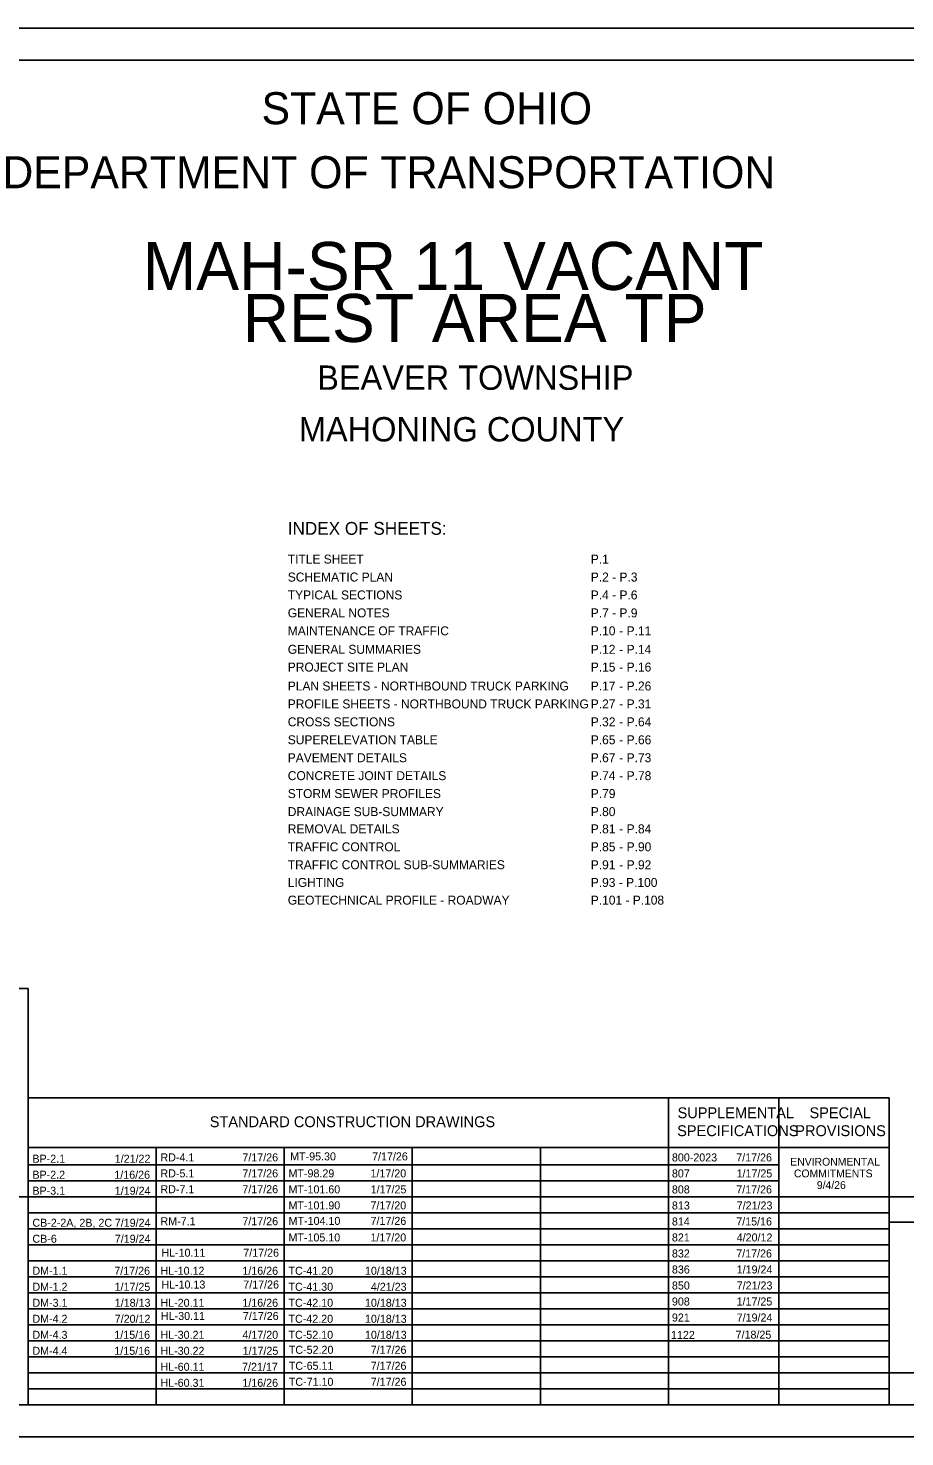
# Model space of a CAD drawing. Extents: x 0 to 36.9, y 0 to 22.
# Drawn here: x 10.15 to 23.84, y 0 to 22 of the extents above; entities that cross this region are included whole.
import ezdxf

# ---------------------------------------------------------------- set-up
doc = ezdxf.new("R2010")
doc.units = 0
for name, color, linetype in [('SH_Border', 7, 'Continuous'), ('SH_Cut_Line', 7, 'Continuous'), ('SH_Data', 7, 'Continuous'), ('SH_Text', 7, 'Continuous')]:
    doc.layers.add(name, color=color, linetype=linetype)

msp = doc.modelspace()

# ---------------------------------------------------------------- linework, layer by layer
at = {"layer": 'SH_Border'}
msp.add_lwpolyline([(1.5, 21.5), (33.5, 21.5), (33.5, 0.5), (1.5, 0.5)], close=True, dxfattribs=at)
at = {"layer": 'SH_Cut_Line'}
msp.add_lwpolyline([(0, 0), (34, 0), (34, 22), (0, 22)], close=True, dxfattribs=at)
at = {"layer": 'SH_Data'}
for p, q in [((10.15, 5.292), (23.6, 5.292)), ((10.15, 0.5), (10.15, 5.292)), ((20.15, 0.5), (20.15, 5.292)), ((21.875, 0.5), (21.875, 5.292)), ((23.6, 0.5), (23.6, 5.292)), ((10.15, 4.521), (23.6, 4.521)), ((12.15, 0.5), (12.15, 4.521)), ((14.15, 0.5), (14.15, 4.521)), ((16.15, 0.5), (16.15, 4.521)), ((18.15, 0.5), (18.15, 4.521)), ((10.15, 4.25), (21.875, 4.25)), ((10.15, 4), (21.875, 4)), ((10.15, 3.75), (23.6, 3.75)), ((23.6, 0.5), (23.6, 3.75)), ((23.6, 3.75), (26.4, 3.75)), ((10.15, 3.5), (23.6, 3.5)), ((23.6, 3.35), (26.4, 3.35)), ((10.15, 3.25), (23.6, 3.25)), ((10.15, 3), (23.6, 3)), ((10.15, 2.75), (23.6, 2.75)), ((10.15, 2.5), (23.6, 2.5)), ((10.15, 2.25), (23.6, 2.25)), ((10.15, 2), (23.6, 2)), ((10.15, 1.75), (23.6, 1.75)), ((10.15, 1.5), (23.6, 1.5)), ((10.15, 1.25), (23.6, 1.25)), ((10.15, 1), (23.6, 1)), ((10.15, 0.75), (23.6, 0.75)), ((23.6, 0.5), (26.4, 0.5))]:
    msp.add_line(p, q, dxfattribs=at)
for points in [[(10.15, 7), (7.35, 7), (7.35, 3.75), (10.15, 3.75)], [(10.15, 3.75), (7.35, 3.75), (7.35, 0.5), (10.15, 0.5)], [(23.6, 0.5), (23.6, 1), (26.4, 1), (26.4, 0.5)]]:
    msp.add_lwpolyline(points, close=True, dxfattribs=at)

# ---------------------------------------------------------------- texts
at = {"layer": 'SH_Text'}
for s, height, p in [('STATE OF OHIO', 0.5, (13.795, 20.5)), ('DEPARTMENT OF TRANSPORTATION', 0.5, (9.747, 19.5)), ('MAH-SR 11 VACANT ', 0.75, (11.94, 17.911)), ('REST AREA TP', 0.75, (13.502, 17.099)), ('BEAVER TOWNSHIP', 0.38, (14.664, 16.352)), ('MAHONING COUNTY', 0.38, (14.378, 15.546)), ('INDEX OF SHEETS:', 0.2, (14.205, 14.088)), ('TITLE SHEET', 0.14, (14.205, 13.638)), ('P.1', 0.14, (18.938, 13.638)), ('SCHEMATIC PLAN', 0.14, (14.205, 13.358)), ('P.2', 0.14, (18.938, 13.358)), ('P.3', 0.14, (19.386, 13.358)), ('TYPICAL SECTIONS', 0.14, (14.205, 13.078)), ('P.4', 0.14, (18.938, 13.078)), (' - ', 0.14, (19.219, 13.358)), ('P.6', 0.14, (19.386, 13.078)), (' - ', 0.14, (19.219, 13.078)), ('GENERAL NOTES', 0.14, (14.205, 12.798)), ('P.7', 0.14, (18.938, 12.798)), (' - ', 0.14, (19.219, 12.798)), ('P.9', 0.14, (19.386, 12.798)), ('MAINTENANCE OF TRAFFIC', 0.14, (14.205, 12.518)), ('P.10', 0.14, (18.938, 12.518)), (' - ', 0.14, (19.331, 12.518)), ('P.11', 0.14, (19.498, 12.518)), ('GENERAL SUMMARIES', 0.14, (14.205, 12.229)), ('P.12', 0.14, (18.938, 12.229)), ('P.14', 0.14, (19.498, 12.229)), (' - ', 0.14, (19.331, 12.229)), ('PROJECT SITE PLAN', 0.14, (14.205, 11.952)), ('P.15', 0.14, (18.938, 11.952)), (' - ', 0.14, (19.331, 11.952)), ('P.16', 0.14, (19.498, 11.952)), ('PLAN SHEETS - NORTHBOUND TRUCK PARKING', 0.14, (14.205, 11.656)), ('P.17', 0.14, (18.938, 11.656)), (' - ', 0.14, (19.331, 11.656)), ('P.26', 0.14, (19.498, 11.656)), ('PROFILE SHEETS - NORTHBOUND TRUCK PARKING', 0.14, (14.205, 11.376)), ('P.27', 0.14, (18.938, 11.376)), ('P.31', 0.14, (19.498, 11.376)), ('CROSS SECTIONS', 0.14, (14.205, 11.096)), ('P.32', 0.14, (18.938, 11.096)), (' - ', 0.14, (19.331, 11.376)), ('P.64', 0.14, (19.498, 11.096)), (' - ', 0.14, (19.331, 11.096)), ('SUPERELEVATION TABLE', 0.14, (14.205, 10.816)), ('P.65', 0.14, (18.938, 10.816)), (' - ', 0.14, (19.331, 10.816)), ('P.66', 0.14, (19.498, 10.816)), ('PAVEMENT DETAILS', 0.14, (14.205, 10.536)), ('P.67', 0.14, (18.938, 10.536)), (' - ', 0.14, (19.331, 10.536)), ('P.73', 0.14, (19.498, 10.536)), ('CONCRETE JOINT DETAILS', 0.14, (14.205, 10.256)), ('P.74', 0.14, (18.938, 10.256)), ('P.78', 0.14, (19.498, 10.256)), (' - ', 0.14, (19.331, 10.256)), ('STORM SEWER PROFILES', 0.14, (14.205, 9.976)), ('P.79', 0.14, (18.938, 9.976)), ('DRAINAGE SUB-SUMMARY', 0.14, (14.205, 9.694)), ('P.80', 0.14, (18.938, 9.694)), ('REMOVAL DETAILS', 0.14, (14.205, 9.425)), ('P.81', 0.14, (18.938, 9.425)), (' - ', 0.14, (19.331, 9.425)), ('P.84', 0.14, (19.498, 9.425)), ('TRAFFIC CONTROL', 0.14, (14.205, 9.145)), ('P.85', 0.14, (18.938, 9.145)), ('P.90', 0.14, (19.498, 9.145)), (' - ', 0.14, (19.331, 9.145)), ('TRAFFIC CONTROL SUB-SUMMARIES', 0.14, (14.205, 8.865)), ('P.91', 0.14, (18.938, 8.864)), (' - ', 0.14, (19.331, 8.864)), ('P.92', 0.14, (19.498, 8.864)), ('LIGHTING', 0.14, (14.205, 8.588)), ('P.93 - P.100', 0.14, (18.938, 8.588)), ('GEOTECHNICAL PROFILE - ROADWAY', 0.14, (14.205, 8.312)), ('P.101 - P.108', 0.14, (18.938, 8.312)), ('SUPPLEMENTAL', 0.17, (20.293, 4.976)), ('SPECIAL', 0.17, (22.354, 4.976)), ('STANDARD CONSTRUCTION DRAWINGS', 0.17, (12.986, 4.836)), ('SPECIFICATIONS', 0.17, (20.287, 4.696)), ('PROVISIONS', 0.17, (22.132, 4.696)), ('BP-2.1', 0.125, (10.216, 4.281)), ('1/21/22', 0.125, (11.502, 4.281)), ('RD-4.1', 0.125, (12.216, 4.302)), ('7/17/26', 0.125, (13.496, 4.302)), ('MT-95.30', 0.125, (14.242, 4.317)), ('7/17/26', 0.125, (15.522, 4.317)), ('800-2023', 0.125, (20.205, 4.301)), ('7/17/26', 0.125, (21.21, 4.301)), ('7/17/26', 0.125, (13.496, 4.052)), ('1/17/20', 0.125, (15.497, 4.052)), ('1/17/25', 0.125, (21.215, 4.051)), ('ENVIRONMENTAL', 0.12154, (22.054, 4.235)), ('BP-2.2', 0.125, (10.216, 4.031)), ('1/16/26', 0.125, (11.496, 4.031)), ('RD-5.1', 0.125, (12.216, 4.052)), ('MT-98.29', 0.125, (14.216, 4.052)), ('807', 0.125, (20.205, 4.051)), ('COMMITMENTS', 0.12154, (22.111, 4.053)), ('9/4/26', 0.1215, (22.469, 3.871)), ('BP-3.1', 0.125, (10.216, 3.781)), ('1/19/24', 0.125, (11.503, 3.781)), ('RD-7.1', 0.125, (12.216, 3.805)), ('7/17/26', 0.125, (13.496, 3.805)), ('MT-101.60', 0.125, (14.216, 3.802)), ('1/17/25', 0.125, (15.5, 3.802)), ('808', 0.125, (20.205, 3.801)), ('7/17/26', 0.125, (21.21, 3.801)), ('MT-101.90', 0.125, (14.216, 3.552)), ('7/17/20', 0.125, (15.497, 3.552)), ('813', 0.125, (20.205, 3.551)), ('7/21/23', 0.125, (21.217, 3.551)), ('CB-2-2A, 2B, 2C', 0.125, (10.216, 3.281)), ('7/19/24', 0.125, (11.503, 3.281)), ('RM-7.1', 0.125, (12.216, 3.305)), ('7/17/26', 0.125, (13.496, 3.305)), ('MT-104.10', 0.125, (14.218, 3.31)), ('7/17/26', 0.125, (15.498, 3.31)), ('814', 0.125, (20.205, 3.301)), ('7/15/16', 0.125, (21.21, 3.301)), ('CB-6', 0.125, (10.216, 3.031)), ('7/19/24', 0.125, (11.503, 3.031)), ('MT-105.10', 0.125, (14.216, 3.051)), ('1/17/20', 0.125, (15.497, 3.051)), ('821', 0.125, (20.205, 3.051)), ('4/20/12', 0.125, (21.217, 3.051)), ('HL-10.11', 0.125, (12.23, 2.813)), ('7/17/26', 0.125, (13.51, 2.813)), ('832', 0.125, (20.205, 2.801)), ('7/17/26', 0.125, (21.21, 2.801)), ('DM-1.1', 0.125, (10.216, 2.531)), ('7/17/26', 0.125, (11.496, 2.531)), ('HL-10.12', 0.125, (12.216, 2.531)), ('1/16/26', 0.125, (13.496, 2.531)), ('TC-41.20', 0.125, (14.216, 2.531)), ('10/18/13', 0.125, (15.411, 2.531)), ('836', 0.125, (20.205, 2.551)), ('1/19/24', 0.125, (21.217, 2.551)), ('HL-10.13', 0.125, (12.23, 2.316)), ('7/17/26', 0.125, (13.51, 2.316)), ('850', 0.125, (20.205, 2.301)), ('7/21/23', 0.125, (21.217, 2.301)), ('DM-1.2', 0.125, (10.216, 2.281)), ('1/17/25', 0.125, (11.5, 2.281)), ('TC-41.30', 0.125, (14.216, 2.281)), ('4/21/23', 0.125, (15.503, 2.281)), ('DM-3.1', 0.125, (10.216, 2.031)), ('1/18/13', 0.125, (11.503, 2.031)), ('HL-20.11', 0.125, (12.216, 2.031)), ('1/16/26', 0.125, (13.496, 2.031)), ('TC-42.10', 0.125, (14.216, 2.031)), ('10/18/13', 0.125, (15.411, 2.031)), ('908', 0.125, (20.205, 2.051)), ('1/17/25', 0.125, (21.215, 2.051)), ('DM-4.2', 0.125, (10.216, 1.781)), ('7/20/12', 0.125, (11.502, 1.781)), ('HL-30.11', 0.125, (12.224, 1.825)), ('7/17/26', 0.125, (13.504, 1.825)), ('TC-42.20', 0.125, (14.216, 1.781)), ('10/18/13', 0.125, (15.411, 1.781)), ('921', 0.125, (20.205, 1.801)), ('7/19/24', 0.125, (21.217, 1.801)), ('DM-4.3', 0.125, (10.216, 1.531)), ('1/15/16', 0.125, (11.496, 1.531)), ('HL-30.21', 0.125, (12.216, 1.531)), ('4/17/20', 0.125, (13.497, 1.531)), ('TC-52.10', 0.125, (14.216, 1.531)), ('10/18/13', 0.125, (15.411, 1.531)), ('1122', 0.125, (20.191, 1.529)), ('7/18/25', 0.125, (21.2, 1.533)), ('DM-4.4', 0.125, (10.216, 1.281)), ('1/15/16', 0.125, (11.496, 1.281)), ('HL-30.22', 0.125, (12.216, 1.281)), ('1/17/25', 0.125, (13.5, 1.281)), ('TC-52.20', 0.125, (14.221, 1.297)), ('7/17/26', 0.125, (15.501, 1.297)), ('HL-60.11', 0.125, (12.216, 1.031)), ('7/21/17', 0.125, (13.491, 1.031)), ('TC-65.11', 0.125, (14.221, 1.047)), ('7/17/26', 0.125, (15.501, 1.047)), ('HL-60.31', 0.125, (12.216, 0.781)), ('1/16/26', 0.125, (13.496, 0.781)), ('TC-71.10', 0.125, (14.221, 0.797)), ('7/17/26', 0.125, (15.501, 0.797))]:
    msp.add_text(s, height=height, dxfattribs=at).set_placement(p)

doc.saveas('drawing.dxf')
